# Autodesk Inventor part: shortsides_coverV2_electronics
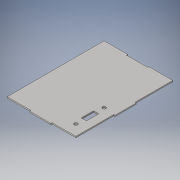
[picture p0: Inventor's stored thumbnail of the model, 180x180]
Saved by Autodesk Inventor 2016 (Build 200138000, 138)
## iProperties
Created: 2015-11
Part Number: shortsides_coverV2_electronics
Material: Generic
Document SubType Name: Modeling
Designer: silverd
Density: 1 g/cm^3
Appearance: Default
Author: silverd
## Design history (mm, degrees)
sketch "Sketch1"
  geometry: L1 (0, 0)-(56.604, 0); L2 (164.008, 0)-(164.008, -231.194); L3 (164.008, -231.194)-(107.404, -231.194); L4 (0, -231.194)-(0, -140.997); L5 (56.604, 3)-(107.404, 3); L6 (107.404, 3)-(107.404, 0); L7 (56.604, 0)-(56.604, 3); L8 (0, -90.197)-(-3, -90.197); L9 (-3, -90.197)-(-3, -140.997); L10 (-3, -140.997)-(0, -140.997); L11 (107.404, 0)-(164.008, 0); L12 (0, -90.197)-(0, 0); L13 (56.604, -231.194)-(0, -231.194); L14 (107.213, -228.194)-(56.794, -228.194); L15 (56.794, -228.194)-(56.794, -231.194); L16 (107.213, -231.194)-(107.213, -228.194); L17 (164.008, -231.194)-(107.213, -231.194); L18 (56.794, -231.194)-(0, -231.194); 2 further points
  constraints: 36 end point, 9 parallel, 7 perpendicular, 5 horizontal
  dimensions: "d0" = 164.0078 distance of L2.end L4.start (= cover_h_nobase); "d1" = 231.1936 distance of L2.start L2.end (= cover_w + acrylic); "d2" = 50.8 distance of L6.end L1.end (= tab_w); "d3" = 3 distance of L5.end L6.end (= acrylic); "d6" = 3 distance of L4.end L9.end (= acrylic); "d7" = 50.8 distance of L9.end L8.end (= tab_w); "d10" = 50.419 distance of L16.start L15.end (= tab_w - t); "d11" = 3 distance of L15.end L14.end (= acrylic)
extrude "Extrusion1" new body sketch "Sketch1" distance "d8" = 3 (= acrylic); taper "d9" = 0 deg
sketch "Sketch2"
  geometry: L1 (-56.604, 0)-(0, 0) reference; L2 (0, 0)-(0, 90.197) reference; L3 (0, 90.197)-(3, 90.197) reference; L4 (3, 90.197)-(3, 140.997) reference; L5 (3, 140.997)-(0, 140.997) reference; L6 (0, 140.997)-(0, 231.194) reference; L7 (0, 231.194)-(-56.794, 231.194) reference; L8 (-56.794, 231.194)-(-56.794, 228.194) reference; L9 (-56.794, 228.194)-(-107.213, 228.194) reference; L10 (-107.213, 228.194)-(-107.213, 231.194) reference; L11 (-107.213, 231.194)-(-164.008, 231.194) reference; L12 (-164.008, 231.194)-(-164.008, 0) reference; L13 (-164.008, 0)-(-107.404, 0) reference; L14 (-107.404, 0)-(-107.404, -3) reference; L15 (-107.404, -3)-(-56.604, -3) reference; L16 (-56.604, -3)-(-56.604, 0) reference; L17 (-19.304, 44.45)-(-31.496, 44.45); L18 (-31.496, 44.45)-(-31.496, 73.66); L19 (-31.496, 73.66)-(-19.304, 73.66); L20 (-19.304, 73.66)-(-19.304, 44.45); C1 r 4.064 at (-25.4, 25.4); C2 r 4.064 at (-25.4, 92.71); 3 further points
  constraints: 8 end point, 2 centre point, 2 midpoint, 2 parallel, 1 horizontal, 1 perpendicular
  dimensions: "d12" = 8.128 diameter of C1 (computed from t); "d13" = 25.4 distance from line of C1.centre L2; "d14" = 25.4 distance from line of C1.centre L1; "d15" = 12.192 distance of L18.end L19.end (computed from t); "d16" = 29.21 distance of L17.end L18.end (computed from t); "d17" = 19.05 distance from line of L17 C1.centre; "d18" = 0 horizontal distance of C1.centre point (-25.4, 44.45); "d19" = 8.128 diameter of C2 (computed from t); "d21" = 19.05 distance of C2.centre point (-25.4, 73.66)
extrude "Extrusion2" cut sketch "Sketch2" distance "d22" = 25.4; taper "d23" = 0 deg
body "Solid1"
node "Projected Loop1"
other parameters: "cover_l" = 291.6936 [user parameter], "cover_w" = 228.1936 [user parameter; used in 1 equation term], "cover_h_nobase" = 164.0078 [user parameter; used in 1 equation term], "acrylic" = 3 [user parameter; used in 5 equation terms], "t" = 0.381 [user parameter; used in 5 equation terms], "tab_w" = 50.8 [user parameter; used in 3 equation terms], "d20" = 0.381 [user parameter]
